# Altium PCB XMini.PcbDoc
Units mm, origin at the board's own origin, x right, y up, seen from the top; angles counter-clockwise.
Board outline 108 x 108 mm, 2 copper layers (Top Layer, Bottom Layer); 86 components, 103 nets, 331 pads, 182 vias.
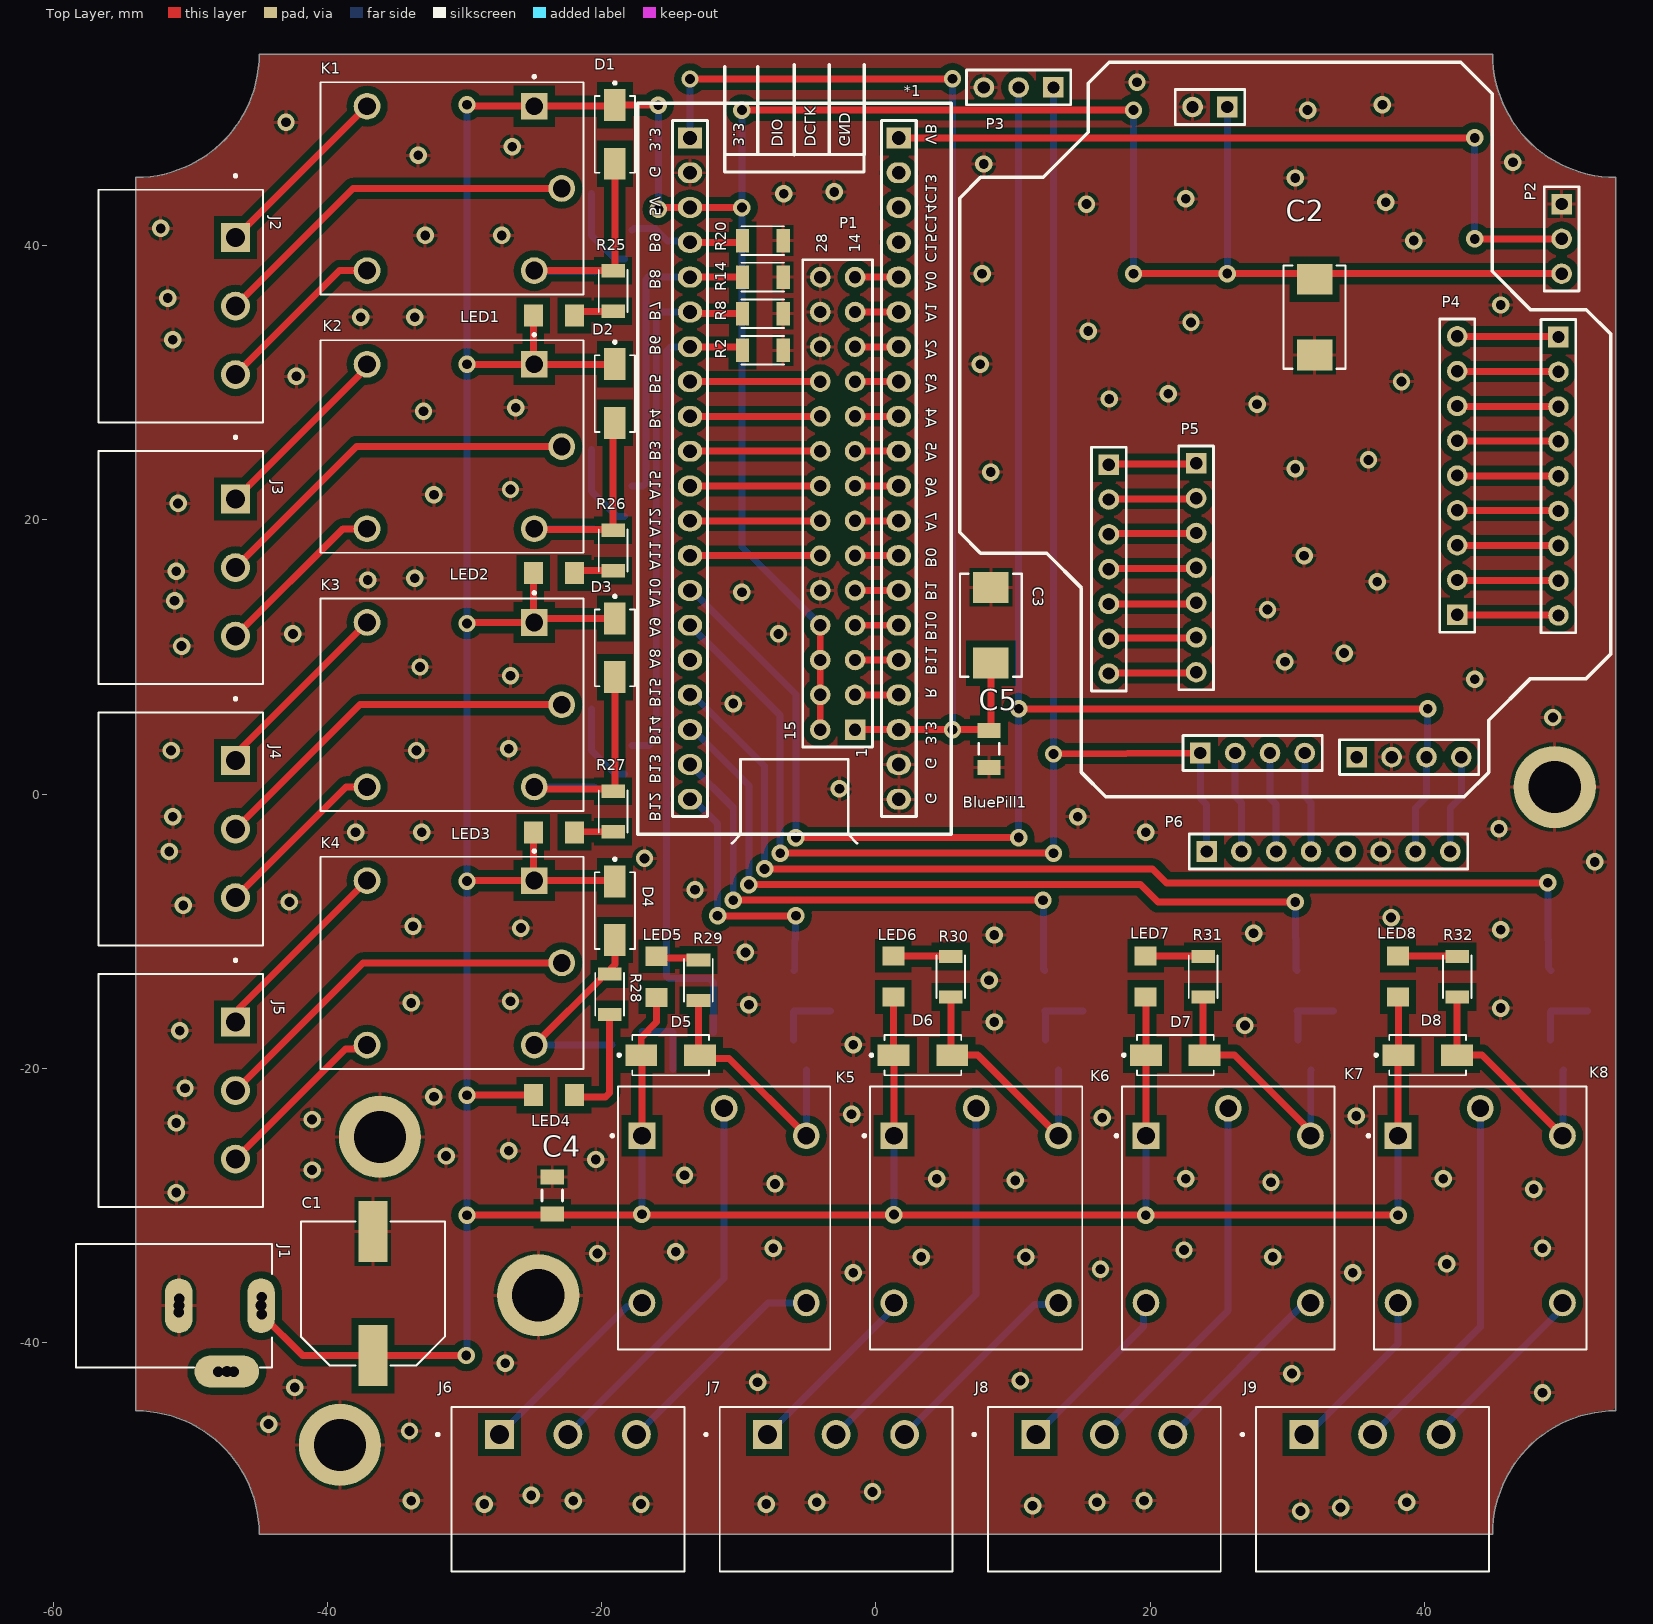
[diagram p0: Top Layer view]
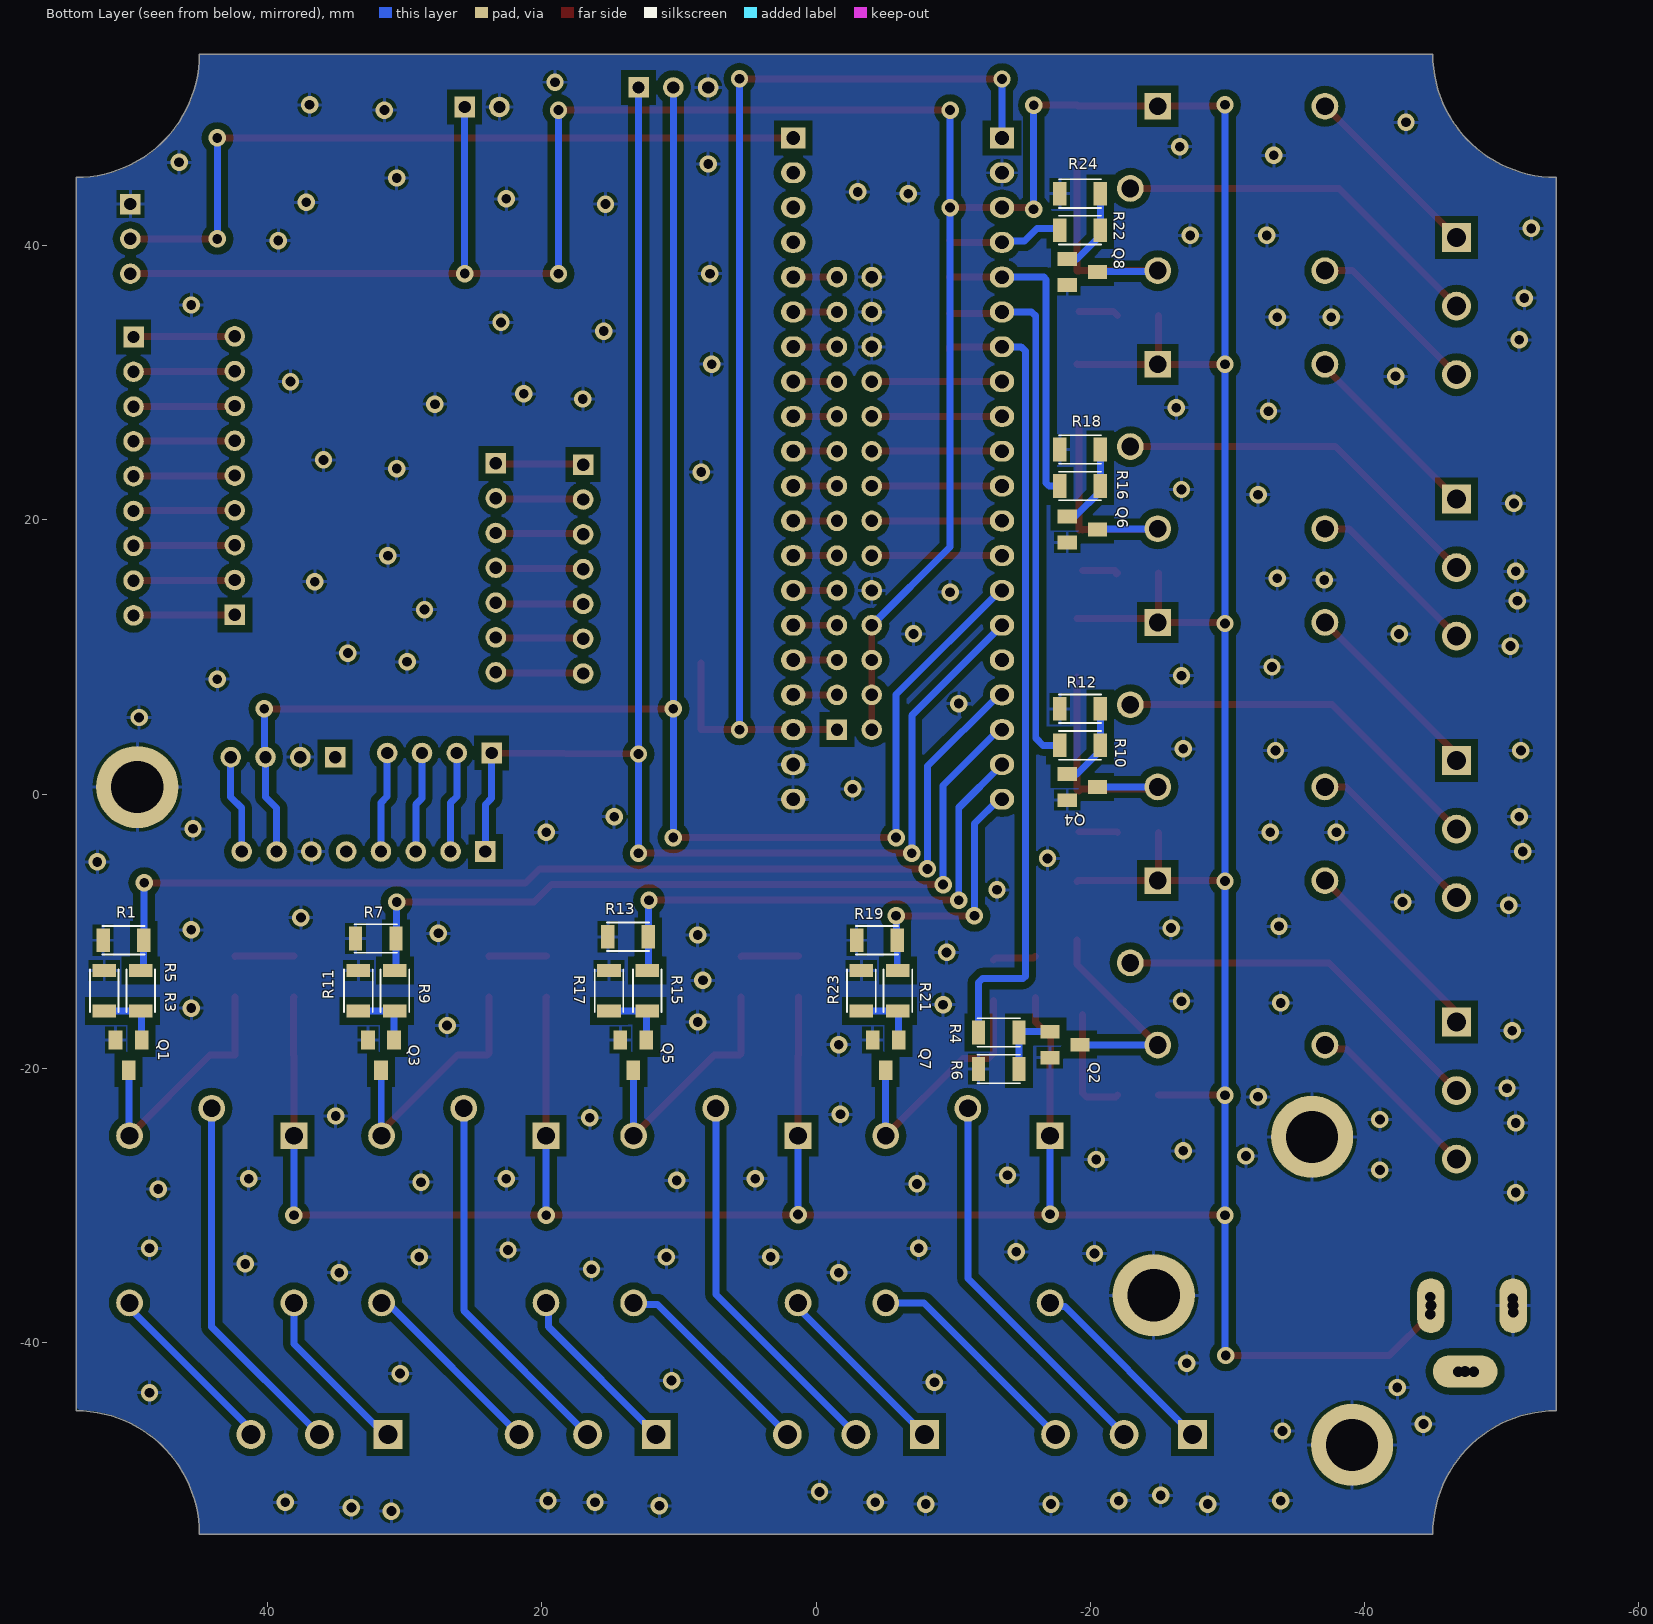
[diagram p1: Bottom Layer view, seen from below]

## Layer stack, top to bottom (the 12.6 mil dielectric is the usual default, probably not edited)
Top Solder: solder mask 0.0102, Solder Resist, Dk 3.5
Top Layer: signal copper 0.0356
Dielectric 1: dielectric 0.32, FR-4, Dk 4.8
Bottom Layer: signal copper 0.0356
Bottom Solder: solder mask 0.0102, Solder Resist, Dk 3.5

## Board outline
-54,-45 -54,45 ccw(c-54,54) -45,54 45,54 ccw(c54,54) 54,45 54,-45 ccw(c54,-54) 45,-54 -45,-54 ccw(c-54,-54)

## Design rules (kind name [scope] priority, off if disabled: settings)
Clearance [All] p1: gap=0.254 ignorepadtopadclearanceinfootprint=FALSE except(0: Arc-Hole Track-Hole SMDPad-Hole THPad-Hole Via-Hole Fill-Hole Poly-Hole Region-Hole Text-Hole; 0.508: Arc-Poly Track-Poly SMDPad-Poly THPad-Poly Via-Poly Fill-Poly Poly-Poly)
PolygonConnect [All] p1: connectstyle=Relief reliefconductorwidth=0.254 reliefentries=4 polygonreliefangle="90 Angle" airgapwidth=0.254
RoutingVias [All] p1: holewidth=0.711 width=1.27 viastyle="Through Hole" minholewidth=0.711 minwidth=1.27 maxholewidth=0.711 maxwidth=1.27
SolderMaskExpansion [All] p1: expansion=0.102
Width [All] p1: maxlimit=0.508 minlimit=0.508 preferedwidth=0.508
30 further rules are at their usual default settings.

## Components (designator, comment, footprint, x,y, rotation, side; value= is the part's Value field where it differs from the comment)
*1 "Component_1" Lora_Board 33.401,26.416 r0 top locked
BluePill1 "BluePill" "stm32 Blue pill" -17.254,-2.794 r0 top locked
C1 "1000uF" *CAPAE1030X1050N -36.703,-36.449 r90 top
C2 "100uF" *CAPCP7343X430N 32.004,34.798 r270 top
C3 "100uF" *CAPCP7343X430N 8.382,12.319 r90 top
C4 "Cap Semi" C1206 -23.622,-29.29 r270 top value=100nF
C5 "Cap Semi" C1206 8.255,3.302 r90 top value=100nF
D1 "S1M" "SMD Diode*DIOM5227X270NSMD DiodeS1MSMD DiodePrimarySMD Diode" -19.05,48.133 r270 top
D2 "S1M" "SMD Diode*DIOM5227X270NSMD DiodeS1MSMD DiodePrimarySMD Diode" -19.05,29.229 r270 top
D3 "S1M" "SMD Diode*DIOM5227X270NSMD DiodeS1MSMD DiodePrimarySMD Diode" -19.05,10.668 r270 top
D4 "S1M" "SMD Diode*DIOM5227X270NSMD DiodeS1MSMD DiodePrimarySMD Diode" -19.05,-8.509 r270 top
D5 "S1M" "SMD Diode*DIOM5227X270NSMD DiodeS1MSMD DiodePrimarySMD Diode" -14.986,-19.05 r0 top
D6 "S1M" "SMD Diode*DIOM5227X270NSMD DiodeS1MSMD DiodePrimarySMD Diode" 3.429,-19.05 r0 top
D7 "S1M" "SMD Diode*DIOM5227X270NSMD DiodeS1MSMD DiodePrimarySMD Diode" 21.844,-19.05 r0 top
D8 "S1M" "SMD Diode*DIOM5227X270NSMD DiodeS1MSMD DiodePrimarySMD Diode" 40.259,-19.05 r0 top
J1 "DC-005" *NINIGI_DC-005 -47.371,-37.338 r0 top locked
J2 "1757488" *PHOENIX_1757488 -46.736,40.687 r270 top locked
J3 "1757488" *PHOENIX_1757488 -46.736,21.606 r270 top locked
J4 "1757488" *PHOENIX_1757488 -46.736,2.524 r270 top locked
J5 "1757488" *PHOENIX_1757488 -46.736,-16.557 r270 top locked
J6 "1757488" *PHOENIX_1757488 -27.559,-46.736 r0 top locked
J7 "1757488" *PHOENIX_1757488 -7.985,-46.736 r0 top locked
J8 "1757488" *PHOENIX_1757488 11.588,-46.736 r0 top locked
J9 "1757488" *PHOENIX_1757488 31.162,-46.736 r0 top locked
K1 "1-1721150-0" *TE_ORWH-SH-105D1F,000 -24.935,50.196 r180 top locked
K2 "1-1721150-0" *TE_ORWH-SH-105D1F,000 -24.935,31.358 r180 top locked
K3 "1-1721150-0" *TE_ORWH-SH-105D1F,000 -24.935,12.519 r180 top locked
K4 "1-1721150-0" *TE_ORWH-SH-105D1F,000 -24.935,-6.319 r180 top locked
K5 "1-1721150-0" *TE_ORWH-SH-105D1F,000 -17.08,-24.935 r270 top locked
K6 "1-1721150-0" *TE_ORWH-SH-105D1F,000 1.313,-24.935 r270 top locked
K7 "1-1721150-0" *TE_ORWH-SH-105D1F,000 19.707,-24.935 r270 top locked
K8 "1-1721150-0" *TE_ORWH-SH-105D1F,000 38.1,-24.935 r270 top locked
LED1 "Red" *LED_597-3111-407F -23.495,34.925 r180 top
LED2 "Red" *LED_597-3111-407F -23.495,16.129 r180 top
LED3 "Red" *LED_597-3111-407F -23.495,-2.794 r180 top
LED4 "Red" *LED_597-3111-407F -23.495,-21.971 r180 top
LED5 "Red" *LED_597-3111-407F -16.002,-13.335 r270 top
LED6 "Red" *LED_597-3111-407F 1.27,-13.31 r270 top
LED7 "Red" *LED_597-3111-407F 19.685,-13.31 r270 top
LED8 "Red" *LED_597-3111-407F 38.1,-13.31 r270 top
P1 "Header 14X2A" HDR2X14_CEN -1.524,4.699 r90 top
P2 "Header 3" HDR1X3 50.038,43.053 r270 top locked
P3 "Header 3" HDR1X3 12.954,51.562 r180 top locked
P4 "Header 9" HDR1X9 42.418,13.081 r90 top locked
P5 "Header 7" HDR1X7 23.368,24.13 r270 top locked
P6 "Header 8" HDR1X8 24.13,-4.191 r0 top locked
Q1 "2N7002" *SOT23 50.165,-19.05 r0 bottom
Q2 "2N7002" *SOT23 -18.161,-18.288 r270 bottom
Q3 "2N7002" *SOT23 31.75,-19.05 r0 bottom
Q4 "2N7002" *SOT23 -19.431,0.508 r270 bottom
Q5 "2N7002" *SOT23 13.335,-19.05 r0 bottom
Q6 "2N7002" *SOT23 -19.431,19.304 r270 bottom
Q7 "2N7002" *SOT23 -5.08,-19.05 r0 bottom
Q8 "2N7002" *SOT23 -19.431,38.1 r270 bottom
R1 "10K" *RESC3116X65N 50.546,-10.668 r0 bottom
R2 "10K" *RESC3116X65N -8.255,32.385 r0 top
R3 "100" *RESC3116X65N 49.276,-14.351 r270 bottom
R4 "100" *RESC3116X65N -13.335,-17.399 r180 bottom
R5 "100K" *RESC3116X65N 51.943,-14.351 r90 bottom
R6 "100K" *RESC3116X65N -13.335,-20.066 r0 bottom
R7 "10K" *RESC3116X65N 32.131,-10.541 r0 bottom
R8 "10K" *RESC3116X65N -8.255,35.052 r0 top
R9 "100" *RESC3116X65N 30.734,-14.351 r270 bottom
R10 "100" *RESC3116X65N -19.266,3.556 r180 bottom
R11 "100K" *RESC3116X65N 33.401,-14.351 r90 bottom
R12 "100K" *RESC3116X65N -19.266,6.223 r0 bottom
R13 "10K" *RESC3116X65N 13.716,-10.414 r0 bottom
R14 "10K" *RESC3116X65N -8.255,37.719 r0 top
R15 "100" *RESC3116X65N 12.319,-14.351 r270 bottom
R16 "100" *RESC3116X65N -19.266,22.479 r180 bottom
R17 "100K" *RESC3116X65N 15.113,-14.351 r90 bottom
R18 "100K" *RESC3116X65N -19.266,25.146 r0 bottom
R19 "10K" *RESC3116X65N -4.445,-10.668 r0 bottom
R20 "10K" *RESC3116X65N -8.255,40.386 r0 top
R21 "100" *RESC3116X65N -5.969,-14.351 r270 bottom
R22 "100" *RESC3116X65N -19.266,41.148 r180 bottom
R23 "100K" *RESC3116X65N -3.302,-14.351 r90 bottom
R24 "100K" *RESC3116X65N -19.266,43.815 r0 bottom
R25 "1K" *RESC3116X65N -19.177,36.703 r90 top
R26 "1K" *RESC3116X65N -19.177,17.78 r90 top
R27 "1K" *RESC3116X65N -19.177,-1.27 r90 top
R28 "1K" *RESC3116X65N -19.431,-14.605 r90 top
R29 "1K" *RESC3116X65N -12.954,-13.589 r270 top
R30 "1K" *RESC3116X65N 5.461,-13.335 r270 top
R31 "1K" *RESC3116X65N 23.876,-13.335 r270 top
R32 "1K" *RESC3116X65N 42.418,-13.335 r270 top

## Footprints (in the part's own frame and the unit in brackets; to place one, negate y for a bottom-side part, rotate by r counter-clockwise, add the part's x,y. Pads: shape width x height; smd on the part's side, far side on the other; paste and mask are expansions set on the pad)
*CAPAE1030X1050N [mm]
  rect 4.46x2.12 smd: 1(-4.525,0) 2(4.525,0)
  silkscreen extent -5.25,-5.25 5.25,5.25
*CAPCP7343X430N [mil]
  rect 89x102 smd: 1(-109,0) 2(109,0)
  silkscreen extent -148,-89 148,89
*LED_597-3111-407F [mil]
  rect 55x63 smd: 1(-59,0) 2(59,0)
*NINIGI_DC-005 [mm]
  oval 4.7x2.35 hole 0.8: 2(0,-4.8)
  oval 2x4 hole 0.8: 3(-3.5,0) 4(2.5,0)
  silkscreen extent -11,-4.5 3.3,4.5
*PHOENIX_1757488 [mm]
  rect 2.1x2.1 hole 1.4: 1(0.08,0)
  round 2.1 hole 1.4: 2(5.08,0) 3(10.08,0)
  silkscreen extent -4.52,-10 13.58,2
*RESC3116X65N [mm]
  rect 0.97x1.73 smd: 1(-1.48,0) 2(1.48,0)
  silkscreen extent -1.55,-1.05 1.55,1.05
*SOT23 [mm]
  rect 1x1.4 smd: 1(-0.95,-1.1) 2(0.95,-1.1) 3(0,1.1)
*TE_ORWH-SH-105D1F,000 [mm]
  rect 1.95x1.95 hole 1.3: 1(0,0)
  round 1.95 hole 1.3: 2(0,12) 3(-2,6) 4(12.2,0) 5(12.2,12)
  silkscreen extent -3.6,-2.26 15.6,13.75
C1206 [mm] "Chip Capacitor, Body 3.2x1.6mm, IPC High Density"
  rect 1.1x1.7 smd: 1(-1.35,0) 2(1.35,0)
  silkscreen extent -0.4,-0.75 0.4,0.75, body extent -1.7,-0.9 1.7,0.9, height 1.3
HDR1X3 [mm] "Connector; Header; 3 Position"
  rect 1.5x1.5 hole 0.9: 1(0,0)
  round 1.5 hole 0.9: 2(2.54,0) 3(5.08,0)
  silkscreen extent -1.27,-1.27 6.35,1.27
HDR1X7 [mm] "Connector; Header; 7 Position"
  rect 1.5x1.5 hole 0.9: 1(0,0)
  round 1.5 hole 0.9: 2(2.54,0) 3(5.08,0) 4(7.62,0) 5(10.16,0) 6(12.7,0) 7(15.24,0)
  silkscreen extent -1.27,-1.27 16.51,1.27
HDR1X8 [mm] "Connector; Header; 8 Position"
  rect 1.5x1.5 hole 0.9: 1(0,0)
  round 1.5 hole 0.9: 2(2.54,0) 3(5.08,0) 4(7.62,0) 5(10.16,0) 6(12.7,0) 7(15.24,0) 8(17.78,0)
  silkscreen extent -1.27,-1.27 19.05,1.27
HDR1X9 [mm] "Connector; Header; 9 Position"
  rect 1.5x1.5 hole 0.9: 1(0,0)
  round 1.5 hole 0.9: 2(2.54,0) 3(5.08,0) 4(7.62,0) 5(10.16,0) 6(12.7,0) 7(15.24,0) 8(17.78,0) 9(20.32,0)
  silkscreen extent -1.27,-1.27 21.59,1.27
HDR2X14_CEN [mm] "Connector; Header; 14x2 Position"
  rect 1.5x1.5 hole 0.9: 1(0,0)
  round 1.5 hole 0.9: 2(2.54,0) 3(5.08,0) 4(7.62,0) 5(10.16,0) 6(12.7,0) 7(15.24,0) 8(17.78,0) 9(20.32,0) 10(22.86,0) 11(25.4,0) 12(27.94,0) 13(30.48,0) 14(33.02,0) 15(0,2.54) 16(2.54,2.54) 17(5.08,2.54) 18(7.62,2.54) 19(10.16,2.54) 20(12.7,2.54) 21(15.24,2.54) 22(17.78,2.54) 23(20.32,2.54) 24(22.86,2.54) 25(25.4,2.54) 26(27.94,2.54) 27(30.48,2.54) 28(33.02,2.54)
  silkscreen extent -1.27,-1.27 34.29,3.81
Lora_Board [mm] "Parvizi Lora Board"
  rect 1.5x1.5 hole 0.9: E1(1.694,-23.722) PA0(-16.404,-2.382) PA3(-9.726,-23.422) PA8(16.404,6.938) VCC(-7.756,23.722)
  round 1.5 hole 0.9: GND(-10.296,23.722) GND(4.234,-23.722) MISO(16.404,-5.762) MOSI(16.404,-8.302) NSS(16.404,-0.682) PA9(16.404,4.398) PA10(16.404,1.858) PA15(-2.106,-23.422) PB3(-4.646,-23.422) PB4(-7.186,-23.422) PB5(-16.404,-17.622) PC13(-16.404,-4.922) SCK(16.404,-3.222) SCL(-16.404,-10.002) SDA(-16.404,-7.462) SWCLK(6.774,-23.722) SWDIO(9.314,-23.722) USART_CTS(16.404,-10.842) USART_RTS(16.404,-13.382) USART_RX(-16.404,-12.542) USART_TX(-16.404,-15.082)
  silkscreen extent -27.29,-26.62 20.2,26.97
"SMD Diode*DIOM5227X270NSMD DiodeS1MSMD DiodePrimarySMD Diode" [mm]
  rect 2.33x1.56 smd: A(2.14,0) C(-2.14,0)
  silkscreen extent -3.85,-1.47 2.8,1.47
"stm32 Blue pill" [mil] "BluePill"
  rect 70x60 hole 39.37: 1(745,1995) 40(145,1995)
  oval 70x60 hole 39.37: 2(745,1895) 3(745,1795) 4(745,1695) 5(745,1595) 6(745,1495) 7(745,1395) 8(745,1295) 9(745,1195) 10(745,1095) 11(745,995) 12(745,895) 13(745,795) 14(745,695) 15(745,595) 16(745,495) 17(745,395) 18(745,295) 19(745,195) 20(745,95) 21(145,95) 22(145,195) 23(145,295) 24(145,395) 25(145,495) 26(145,595) 27(145,695) 28(145,795) 29(145,895) 30(145,995) 31(145,1095) 32(145,1195) 33(145,1295) 34(145,1395) 35(145,1495) 36(145,1595) 37(145,1695) 38(145,1795) 39(145,1895)
  silkscreen extent -5,-32 895,2205

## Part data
BluePill1: library part Stm32BluePill, "Blue Pill Module"
C1: library part HZA107M050G24T-F, "Cap Aluminum Polymer Hybrid 100uF 50VDC 20% _10 X 10.2mm_ SMD 0.028 Ohm 2000mA 10000h 105C Automotive T/R", Package="Radial Cornell Dubilier"
C2 C3: library part TAJE337K006R, "Capacitor tantalum TAJ 2717 330uF 6.3V", Package=None
C4 C5: "Capacitor (Semiconductor SIM Model)"
D1 D2 D3 D4 D5 D6 D7 D8: "S1 Series 1000 V 1 A 1 uA Surface Mount General Purpose Rectifier - DO-214AC", Package="DO-214AC-214 ON Semiconductor"
J1: Package="0603 Ninigi"
J2 J3 J4 J5 J6 J7 J8 J9: "Conn; TermBlk; PCB; Header; SnglLvl; 90DegAngl; Sldr; 3Pole; 5mmPitch; COMBICON", Package=None
K1 K2 K3 K4 K5 K6 K7 K8: library part ORWH-SH-105D1F,000, "General Purpose Relay, ORWH Series, Power, Non Latching, SPDT, 5 VDC, 10 A", Package=None
LED1 LED2 LED3 LED4 LED5 LED6 LED7 LED8: library part 597-3111-407F, "LED RED CLEAR 1206 SMD", Package="1206 Dialight"
P1: "Header, 14-Pin, Dual row"
P2 P3: "Header, 3-Pin"
P4: "Header, 9-Pin"
P5: "Header, 7-Pin"
P6: "Header, 8-Pin"
Q1 Q2 Q3 Q4 Q5 Q6 Q7 Q8: "Transistor NPN Mos 2N7002 SILICONIX miliampere=100 V=60 SOt23", Package="SOT-23-3 Vishay"
R1 R2 R3 R4 R5 R6 R7 R8 R9 R10 R11 R12 R13 R14 R15 R16 R17 R18 R19 R20 R21 R22 R23 R24 R25 R26 R27 R28 R29 R30 R31 R32: library part RT1206DRE07120KL, "Res Smd 120k Ohm 0.5% 1/8w 1206", Package="1206 Yageo"

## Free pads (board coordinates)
  round 1.524 hole 0.762: 2(-44.831,-37.973) 3(-44.831,-36.703) 4(-46.863,-42.164) 5(-48.006,-42.164) 6(-50.876,-37.821) 7(-50.851,-36.83)
  round 6 hole 3.81: 5(-39.116,-47.498) 5(-36.195,-25.019) 5(-24.638,-36.576) 5(49.53,0.508)

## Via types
v1: diameter 1.27, hole 0.711, Top Layer to Bottom Layer, tented both sides, 182 vias

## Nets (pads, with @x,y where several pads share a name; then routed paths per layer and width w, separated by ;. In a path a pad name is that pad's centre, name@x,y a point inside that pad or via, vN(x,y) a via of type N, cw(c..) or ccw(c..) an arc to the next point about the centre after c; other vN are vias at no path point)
3.3V: BluePill1.18 BluePill1.40 C3.1 C5.2 P1.1 | length 85.7
  Top Layer w0.508: v1(-13.571,52.179) 5.57,52.179 v1(5.588,52.197) ; P1.1 BluePill1.18 v1(5.588,4.699) 8.382,4.699 C3.1
  Bottom Layer w0.508: v1@-13.589,52.197 v1(-13.571,52.179) BluePill1.40 ; v1(5.588,4.699) v1(5.588,52.197)
5V: *1.VCC BluePill1.38 C1.1 C2.1 C4.2 D1.C D2.C D3.C D4.C D5.C D6.C D7.C D8.C J1.4 K1.1 K2.1 K3.1 K4.1 K5.1 K6.1 K7.1 K8.1 LED1.2 LED2.2 LED3.2 LED4.2 LED5.2 LED6.2 LED7.2 LED8.2 P1.15 P1.16 P1.17 P1.18 P2.3 pad.2 pad.3 | length 447.2
  Top Layer w0.508: pad.2 -41.83,-40.974 C1.1 v1(-29.892,-40.974) ; v1(-29.845,-30.734) v1(19.685,-30.734) v1@37.973,-30.734 ; v1(-29.845,-21.971) LED4.2 ; v1(-29.845,-6.35) -29.814,-6.319 K4.1 ; v1@-29.845,12.573 -29.791,12.519 K3.1 ; v1(-29.845,31.369) -29.834,31.358 K2.1 ; v1@-29.845,50.165 -29.814,50.196 K1.1 -19.127,50.196 D1.C v1(-15.894,50.273) v1@-15.875,50.292 ; LED3.2 -24.994,-6.26 K4.1 ; LED2.2 -24.994,12.578 K3.1 ; LED1.2 -24.994,31.416 K2.1 ; D4.C -19.1,-6.319 K4.1 ; D3.C -24.646,12.808 K3.1 ; D2.C -19.061,31.358 K2.1 ; K5.1 -17.08,-19.096 D5.C -17.126,-17.761 -16.002,-16.637 LED5.2 ; v1@-16.129,42.799 BluePill1.38 v1(-9.779,42.799) ; v1(-9.779,49.911) v1(18.796,49.911) ; P1.15 P1.16 P1.17 P1.18 ; LED6.2 1.289,-14.827 D6.C 1.313,-19.074 K6.1 ; v1(18.796,37.973) P2.3 ; LED7.2 19.704,-14.827 D7.C 19.707,-19.053 K7.1 ; K8.1 38.1,-19.069 D8.C 38.119,-14.827 LED8.2
  Bottom Layer w0.508: v1@-29.845,-40.974 v1(-29.845,-30.734) v1(-29.845,-21.971) v1(-29.845,-6.35) v1(-29.845,12.446) v1(-29.845,31.369) v1(-29.845,50.292) ; v1@-17.145,-30.734 v1(-17.08,-30.669) K5.1 ; v1(-15.875,42.672) v1@-15.875,50.292 ; v1(-9.779,49.911) v1(-9.779,42.799) -9.779,18.034 P1.18 ; v1@1.27,-30.734 v1(1.313,-30.691) K6.1 ; v1(18.796,37.973) v1(18.796,49.911) ; v1(19.685,-30.734) 19.707,-30.712 K7.1 ; *1.VCC v1(25.645,37.982) v1@25.654,37.973 ; v1(38.1,-30.734) K8.1
GND: *1.GND BluePill1.19 BluePill1.20 BluePill1.39 C1.2 C2.2 C3.2 C4.1 C5.1 J1.3 P1.19 P1.26 P1.27 P1.28 P2.1 P3.3 P6.6 pad.5@49.53,0.508 pad.5@-24.638,-36.576 pad.5@-36.195,-25.019 pad.5@-39.116,-47.498 pad.6 pad.7 Q1.2 Q2.2 Q3.2 Q4.2 Q5.2 Q6.2 Q7.2 Q8.2 R1.2 R2.2 R5.2 R6.2 R7.2 R8.2 R11.2 R12.2 R13.2 R14.2 R17.2 R18.2 R19.2 R20.2 R23.2 R24.2
  other v1: 30.988,-52.324 33.909,-52.07 11.43,-51.943 -28.575,-51.816 -17.145,-51.816 -8.001,-51.816 -4.318,-51.689 16.129,-51.689 38.735,-51.689 -33.909,-51.562 -22.098,-51.562 19.558,-51.562 -25.146,-51.181 -0.254,-50.927 -34.036,-46.482 -44.323,-45.974 48.641,-43.688 -42.418,-43.307 -8.636,-42.926 10.541,-42.799 30.353,-42.291 -27.051,-41.529 -1.651,-34.925 34.798,-34.925 16.383,-34.671 41.656,-34.29 3.302,-33.782 10.922,-33.782 28.956,-33.782 -20.32,-33.528 -14.605,-33.401 22.479,-33.274 -7.493,-33.147 48.641,-33.147 -51.054,-29.083 48.006,-28.829 -7.366,-28.448 28.829,-28.321 10.16,-28.194 4.445,-28.067 22.606,-28.067 41.402,-28.067 -13.97,-27.813 -41.148,-27.432 -20.447,-26.67 -31.369,-26.416 -26.797,-26.035 -51.054,-24.003 -41.148,-23.749 16.51,-23.622 35.052,-23.495 -1.778,-23.368 -32.258,-22.098 -50.419,-21.463 -1.651,-18.288 -50.8,-17.272 26.924,-16.891 8.636,-16.637 45.593,-15.621 -9.271,-15.367 -33.909,-15.24 -26.67,-15.113 8.255,-13.589 -9.525,-11.557 8.636,-10.287 27.559,-10.16 45.593,-9.906 -25.908,-9.779 -33.782,-9.652 37.592,-9.017 -50.546,-8.128 -42.799,-7.874 -13.208,-6.985 52.451,-4.953 -16.891,-4.699 -51.562,-4.191 -37.973,-2.794 -33.147,-2.794 19.685,-2.794 45.466,-2.54 -51.308,-1.651 14.732,-1.651 -2.667,0.381 -51.435,3.175 -33.528,3.175 -26.797,3.302 49.403,5.588 -10.414,6.604 43.688,8.382 -26.67,8.636 -33.274,9.271 29.845,9.652 34.163,10.287 -50.673,10.795 -42.545,11.684 -7.112,11.684 28.575,13.462 -51.181,14.097 -9.779,14.732 36.576,15.494 -37.084,15.621 -33.655,15.748 -51.054,16.256 31.242,17.399 -50.927,21.209 -32.258,21.844 -26.67,22.225 8.382,23.495 30.607,23.749 35.941,24.384 -33.02,27.94 -26.289,28.194 27.813,28.448 17.018,28.829 21.336,29.21 38.354,30.099 -42.291,30.48 7.62,31.369 -51.308,33.147 15.494,33.782 22.987,34.417 -37.592,34.798 -33.655,34.798 45.593,35.687 -51.689,36.195 7.747,37.973 39.243,40.386 -32.893,40.767 -27.305,40.767 -52.197,41.275 15.367,43.053 37.211,43.18 22.606,43.434 -6.731,43.815 -3.048,43.942 30.607,44.958 7.874,45.974 46.482,46.101 -33.401,46.609 -26.543,47.244 -43.053,49.022 31.496,49.911 36.957,50.292 19.05,51.943
LPA0: *1.PA0 P5.1 | length 6.4
  Top Layer w0.508: *1.PA0 17.045,24.082 23.32,24.082 P5.1
LPA3: *1.PA3 BluePill1.26 P3.1 P6.1 | length 113.3
  Top Layer w0.508: v1(-6.985,-4.318) v1(12.954,-4.318) ; v1(12.954,2.921) *1.PA3
  Bottom Layer w0.508: BluePill1.26 -6.985,5.733 v1(-6.985,-4.318) ; v1(12.954,-4.318) v1(12.954,2.921) P3.1 ; *1.PA3 23.675,-0.307 24.13,-0.762 P6.1
LPA8: *1.PA8 P4.9 | length 7.4
  Top Layer w0.508: P4.9 42.441,33.378 49.781,33.378 *1.PA8
LPA9: *1.PA9 P4.8 | length 7.4
  Top Layer w0.508: P4.8 42.441,30.838 49.781,30.838 *1.PA9
LPA10: *1.PA10 P4.7 | length 7.4
  Top Layer w0.508: P4.7 42.441,28.298 49.781,28.298 *1.PA10
LPA15: *1.PA15 P6.4 | length 7.4
  Bottom Layer w0.508: *1.PA15 31.295,-0.18 31.75,-0.635 P6.4
LPB3: *1.PB3 P6.3 | length 7.4
  Bottom Layer w0.508: *1.PB3 28.755,-0.307 29.21,-0.762 P6.3
LPB4: *1.PB4 P6.2 | length 7.4
  Bottom Layer w0.508: *1.PB4 26.215,-0.18 26.67,-0.635 P6.2
LPB5: *1.PB5 P5.7 | length 6.4
  Top Layer w0.508: *1.PB5 17.045,8.842 23.32,8.842 P5.7
LPC13: *1.PC13 P5.2 | length 6.4
  Top Layer w0.508: *1.PC13 17.045,21.542 23.32,21.542 P5.2
MISO: *1.MISO P4.4 | length 7.4
  Top Layer w0.508: P4.4 42.441,20.678 49.781,20.678 *1.MISO
MOSI: *1.MOSI P4.3 | length 7.4
  Top Layer w0.508: P4.3 42.441,18.138 49.781,18.138 *1.MOSI
NC: P6.5
NetJ2_1: J2.1 K1.4 | length 13.6
  Top Layer w0.508: J2.1 -37.147,50.196 K1.4
NetJ2_2: J2.2 K1.3 | length 27.4
  Top Layer w0.508: J2.2 -38.147,44.196 K1.3
NetJ2_3: J2.3 K1.5 | length 12.7
  Top Layer w0.508: J2.3 -39.147,38.196 K1.5
NetJ3_1: J3.1 K2.4 | length 13.8
  Top Layer w0.508: J3.1 -37.135,31.127 K2.4
NetJ3_2: J3.2 K2.3 | length 27.5
  Top Layer w0.508: J3.2 -37.904,25.358 K2.3
NetJ3_3: J3.3 K2.5 | length 12.8
  Top Layer w0.508: J3.3 -38.904,19.358 K2.5
NetJ4_1: J4.1 K3.4 | length 14.1
  Top Layer w0.508: J4.1 -46.736,2.918 K3.4
NetJ4_2: J4.2 K3.3 | length 27.6
  Top Layer w0.508: J4.2 -37.661,6.519 K3.3
NetJ4_3: J4.3 K3.5 | length 12.9
  Top Layer w0.508: J4.3 -38.661,0.519 K3.5
NetJ5_1: J5.1 K4.4 | length 14.3
  Top Layer w0.508: J5.1 -46.736,-15.92 K4.4
NetJ5_2: J5.2 K4.3 | length 27.7
  Top Layer w0.508: J5.2 -37.418,-12.319 K4.3
NetJ5_3: J5.3 K4.5 | length 13
  Top Layer w0.508: J5.3 -38.694,-18.595 -37.411,-18.595 K4.5
NetJ6_1: J6.1 K5.4 | length 14.4
  Bottom Layer w0.508: J6.1 -18.154,-37.411 -17.356,-37.411 K5.4
NetJ6_2: J6.2 K5.3 | length 28.5
  Bottom Layer w0.508: J6.2 -11.08,-35.337 K5.3
NetJ6_3: J6.3 K5.5 | length 16.4
  Bottom Layer w0.508: J6.3 -7.878,-37.135 K5.5
NetJ7_1: J7.1 K6.4 | length 13.4
  Bottom Layer w0.508: J7.1 1.313,-37.517 K6.4
NetJ7_2: J7.2 K6.3 | length 28
  Bottom Layer w0.508: J7.2 7.313,-36.517 K6.3
NetJ7_3: J7.3 K6.5 | length 15.2
  Bottom Layer w0.508: J7.3 11.576,-37.254 13.194,-37.254 K6.5
NetJ8_1: J8.1 K7.4 | length 12.9
  Bottom Layer w0.508: J8.1 19.533,-38.872 19.533,-37.309 K7.4
NetJ8_2: J8.2 K7.3 | length 27.5
  Bottom Layer w0.508: J8.2 25.707,-37.698 K7.3
NetJ8_3: J8.3 K7.5 | length 14.1
  Bottom Layer w0.508: J8.3 31.32,-37.084 31.656,-37.084 K7.5
NetJ9_1: J9.1 K8.4 | length 12.6
  Bottom Layer w0.508: J9.1 31.496,-46.736 38.1,-40.132 K8.4
NetJ9_2: J9.2 K8.3 | length 27.1
  Bottom Layer w0.508: J9.2 44.1,-38.878 K8.3
NetJ9_3: J9.3 K8.5 | length 13.3
  Bottom Layer w0.508: J9.3 41.242,-46.364 50.1,-37.506 K8.5
NetLED1_1: LED1.1 R25.1 | length 2.9
  Top Layer w0.508: LED1.1 -21.698,35.223 R25.1
NetLED2_1: LED2.1 R26.1 | length 2.8
  Top Layer w0.508: LED2.1@-21.913,16.046 LED2.1 -21.825,16.3 R26.1@-19.431,16.3
NetLED3_1: LED3.1 R27.1 | length 2.8
  Top Layer w0.508: LED3.1 -21.952,-2.75 R27.1
NetLED4_1: LED4.1 R28.1 | length 8.5
  Top Layer w0.508: LED4.1 -21.869,-22.098 -19.729,-22.098 -19.431,-21.8 R28.1
NetLED5_1: LED5.1 R29.1 | length 3.2
  Top Layer w0.508: LED5.1 -15.866,-11.973 -13.09,-11.973 R29.1
NetLED6_1: LED6.1 R30.1 | length 4.2
  Top Layer w0.508: LED6.1 1.292,-11.833 5.439,-11.833 R30.1
NetLED7_1: LED7.1 R31.1 | length 4.2
  Top Layer w0.508: LED7.1 19.707,-11.833 23.854,-11.833 R31.1
NetLED8_1: LED8.1 R32.1 | length 4.3
  Top Layer w0.508: LED8.1 38.122,-11.833 42.396,-11.833 R32.1
NetQ1_1: Q1.1 R3.2 R5.1 | length 4.8
  Bottom Layer w0.508: Q1.1 49.215,-15.892 R3.2 R5.1
NetQ2_1: Q2.1 R4.2 R6.1 | length 4.9
  Bottom Layer w0.508: Q2.1 -14.876,-17.338 R4.2 R6.1
NetQ3_1: Q3.1 R9.2 R11.1 | length 4.8
  Bottom Layer w0.508: Q3.1 30.8,-15.897 R9.2 R11.1
NetQ4_1: Q4.1 R10.2 R12.1 | length 6.2
  Bottom Layer w0.508: R12.1 R10.2 -20.746,3.176 -19.028,1.458 Q4.1
NetQ5_1: Q5.1 R15.2 R17.1 | length 4.9
  Bottom Layer w0.508: Q5.1 12.385,-15.897 R15.2 R17.1
NetQ6_1: Q6.1 R16.2 R18.1 | length 6.2
  Bottom Layer w0.508: R18.1 R16.2 -20.746,22.099 -18.901,20.254 Q6.1
NetQ7_1: Q7.1 R21.2 R23.1 | length 4.8
  Bottom Layer w0.508: Q7.1 -6.03,-15.892 R21.2 R23.1
NetQ8_1: Q8.1 R22.2 R24.1 | length 6.2
  Bottom Layer w0.508: R24.1 R22.2 -20.746,40.768 -19.028,39.05 Q8.1
NSS: *1.NSS P4.6 | length 7.4
  Top Layer w0.508: P4.6 42.441,25.758 49.781,25.758 *1.NSS
PA0: BluePill1.5 P1.14 | length 3.2
  Top Layer w0.508: P1.14 BluePill1.5
PA1: BluePill1.6 P1.13 | length 3.2
  Top Layer w0.508: P1.13 BluePill1.6
PA2: BluePill1.7 P1.12 | length 3.2
  Top Layer w0.508: P1.12 BluePill1.7
PA3: BluePill1.8 P1.11 | length 3.2
  Top Layer w0.508: P1.11 BluePill1.8
PA4: BluePill1.9 P1.10 | length 3.2
  Top Layer w0.508: P1.10 BluePill1.9
PA5: BluePill1.10 P1.9 | length 3.2
  Top Layer w0.508: P1.9 BluePill1.10
PA6: BluePill1.11 P1.8 | length 3.2
  Top Layer w0.508: P1.8 BluePill1.11
PA7: BluePill1.12 P1.7 | length 3.2
  Top Layer w0.508: P1.7 BluePill1.12
PA8: BluePill1.25
PA11: BluePill1.28 P1.20 | length 9.5
  Top Layer w0.508: BluePill1.28 P1.20
PA12: BluePill1.29 P1.21 | length 9.5
  Top Layer w0.508: BluePill1.29 P1.21
PA15: BluePill1.30 P1.22 | length 9.5
  Top Layer w0.508: BluePill1.30 P1.22
PB0: BluePill1.13 P1.6 | length 3.2
  Top Layer w0.508: P1.6 BluePill1.13
PB1: BluePill1.14 P1.5 | length 3.2
  Top Layer w0.508: P1.5 BluePill1.14
PB3: BluePill1.31 P1.23 | length 9.5
  Top Layer w0.508: BluePill1.31 P1.23
PB4: BluePill1.32 P1.24 | length 9.5
  Top Layer w0.508: BluePill1.32 P1.24
PB5: BluePill1.33 P1.25 | length 9.5
  Top Layer w0.508: BluePill1.33 P1.25
PB6: BluePill1.34 R2.1 R4.1 | length 58.8
  Top Layer w0.508: BluePill1.34 -9.735,32.639 R2.1
  Bottom Layer w0.508: BluePill1.34 -14.971,32.639 -15.269,32.341 -15.269,-13.306 -15.113,-13.462 -12.153,-13.462 -11.855,-13.76 R4.1
PB7: BluePill1.35 R8.1 R10.1 | length 39.2
  Top Layer w0.508: BluePill1.35 -13.444,35.052 R8.1
  Bottom Layer w0.508: R10.1 -16.554,3.556 -16.031,4.079 -16.031,34.881 -15.733,35.179 BluePill1.35
PB8: BluePill1.36 R14.1 R16.1 | length 23.1
  Top Layer w0.508: BluePill1.36 R14.1
  Bottom Layer w0.508: R16.1 -17.018,22.479 -16.793,22.704 -16.793,37.563 -16.637,37.719 BluePill1.36
PB9: BluePill1.37 R20.1 R22.1 | length 8.6
  Top Layer w0.508: BluePill1.37 -9.862,40.259 R20.1
  Bottom Layer w0.508: R22.1 -17.659,41.275 -16.129,41.275 -15.222,40.368 -13.68,40.368 BluePill1.37
PB10: BluePill1.15 P1.4 | length 3.2
  Top Layer w0.508: P1.4 BluePill1.15
PB11: BluePill1.16 P1.3 | length 3.2
  Top Layer w0.508: P1.3 BluePill1.16
PB12: BluePill1.21 R19.1 R21.1 | length 19.2
  Top Layer w0.508: v1(-11.557,-8.89) v1(-5.842,-8.89)
  Bottom Layer w0.508: BluePill1.21 -13.335,-0.381 -11.557,-2.159 v1(-11.557,-8.89) ; R21.1 -5.925,-12.827 R19.1 -5.884,-10.626 -5.884,-8.932 v1(-5.842,-8.89)
PB13: BluePill1.22 R13.1 R15.1 | length 39.5
  Top Layer w0.508: v1(-10.414,-7.747) v1(12.192,-7.747)
  Bottom Layer w0.508: BluePill1.22 -10.414,-0.998 v1(-10.414,-7.747) ; v1(12.192,-7.747) 12.214,-7.515 12.214,-10.392 R13.1 12.236,-12.788 R15.1
PB14: BluePill1.23 R7.1 R9.1 | length 58.7
  Top Layer w0.508: v1(-9.271,-6.604) 12.665,-6.604 19.304,-6.604 20.574,-7.874 v1(30.607,-7.874)
  Bottom Layer w0.508: BluePill1.23 -13.335,4.699 -9.271,0.635 v1(-9.271,-6.604) ; v1(30.607,-7.874) 30.629,-7.896 30.629,-10.519 R7.1 30.651,-12.788 R9.1
PB15: BluePill1.24 R1.1 R3.1 | length 79.2
  Top Layer w0.508: v1(-8.128,-5.461) 20.193,-5.461 21.209,-6.477 v1(49.022,-6.477)
  Bottom Layer w0.508: BluePill1.24 -13.335,7.239 -8.128,2.032 v1(-8.128,-5.461) ; v1(49.022,-6.477) 49.044,-6.499 49.044,-10.646 R1.1 49.066,-12.661 R3.1
"Relay 1": D1.A K1.2 Q8.3 R25.2 | length 18
  Top Layer w0.508: K1.2 -24.928,38.19 -19.184,38.19 R25.2 ; R25.2@-19.05,38.183 D1.A
  Bottom Layer w0.508: K1.2 -24.887,38.148 -20.579,38.148 Q8.3
"Relay 2": D2.A K2.2 Q6.3 R26.2 | length 17.8
  Top Layer w0.508: K2.2 -24.886,19.309 -19.48,19.309 R26.2@-19.431,19.26 ; R26.2 -19.177,26.962 D2.A
  Bottom Layer w0.508: K2.2@-24.908,19.331 -20.558,19.331 Q6.3
"Relay 3": D3.A K3.2 Q4.3 R27.2 | length 18.5
  Top Layer w0.508: K3.2 -24.78,0.365 -19.332,0.365 R27.2 ; R27.2@-19.05,0.287 D3.A
  Bottom Layer w0.508: K3.2 -24.929,0.514 -20.537,0.514 Q4.3
"Relay 4": D4.A K4.2 Q2.3 R28.2 | length 15.8
  Top Layer w0.508: K4.2 -19.741,-13.125 -19.05,-12.434 D4.A
  Bottom Layer w0.508: K4.2 -24.919,-18.303 -19.277,-18.303 Q2.3
"Relay 5": D5.A K5.2 Q7.3 R29.2 | length 19
  Top Layer w0.508: R29.2 -12.954,-18.942 D5.A -12.592,-19.304 -10.711,-19.304 K5.2
  Bottom Layer w0.508: K5.2 Q7.3
"Relay 6": D6.A K6.2 Q5.3 R30.2 | length 19.3
  Top Layer w0.508: R30.2 5.461,-18.942 D6.A 7.429,-19.05 K6.2
  Bottom Layer w0.508: K6.2 13.324,-24.924 13.324,-20.161 Q5.3
"Relay 7": D7.A K7.2 Q3.3 R31.2 | length 19.4
  Top Layer w0.508: R31.2 23.876,-18.942 D7.A 26.162,-19.05 31.707,-24.595 K7.2
  Bottom Layer w0.508: K7.2 31.728,-24.913 31.728,-20.172 Q3.3
"Relay 8": D8.A K8.2 Q1.3 R32.2 | length 19.2
  Top Layer w0.508: R32.2 42.399,-14.834 D8.A 44.215,-19.05 K8.2
  Bottom Layer w0.508: K8.2 50.132,-24.902 50.132,-20.183 Q1.3
Reset: BluePill1.17 P1.2 | length 3.2
  Top Layer w0.508: P1.2 BluePill1.17
RX1: *1.SWCLK BluePill1.27 P3.2 P6.7 | length 132.9
  Top Layer w0.508: v1(-5.842,-3.175) v1(10.414,-3.175) ; v1(10.414,6.223) v1(40.259,6.223)
  Bottom Layer w0.508: BluePill1.27 -13.444,14.859 -5.842,7.257 v1(-5.842,-3.175) ; v1(10.414,-3.175) v1(10.414,6.223) P3.2 ; P6.7 39.37,-1.016 40.175,-0.211 *1.SWCLK 40.259,2.778 v1(40.259,6.223)
SCK: *1.SCK P4.5 | length 7.4
  Top Layer w0.508: P4.5 42.441,23.218 49.781,23.218 *1.SCK
SCL: *1.SCL P5.4 | length 6.4
  Top Layer w0.508: *1.SCL 17.045,16.462 23.32,16.462 P5.4
SDA: *1.SDA P5.3 | length 6.4
  Top Layer w0.508: *1.SDA 17.045,19.002 23.32,19.002 P5.3
SWDIO: *1.SWDIO P6.8 | length 7.2
  Bottom Layer w0.508: P6.8 41.91,-1.016 42.715,-0.211 *1.SWDIO
USART_CTS: *1.USART_CTS P4.2 | length 7.4
  Top Layer w0.508: P4.2 42.441,15.598 49.781,15.598 *1.USART_CTS
USART_RTS: *1.USART_RTS P4.1 | length 7.4
  Top Layer w0.508: P4.1 42.441,13.058 49.781,13.058 *1.USART_RTS
USART_RX: *1.USART_RX P5.5 | length 6.5
  Top Layer w0.508: *1.USART_RX@17.045,13.922 *1.USART_RX 23.272,13.874 P5.5
USART_TX: *1.USART_TX P5.6 | length 6.4
  Top Layer w0.508: *1.USART_TX 17.045,11.382 23.32,11.382 P5.6
VB: BluePill1.1 P2.2 | length 55.7
  Top Layer w0.508: BluePill1.1 v1(43.688,47.879) ; v1(43.688,40.513) P2.2
  Bottom Layer w0.508: v1(43.688,40.513) v1(43.688,47.879)
pads on no net: *1.E1 BluePill1.2 BluePill1.3 BluePill1.4 J1.2

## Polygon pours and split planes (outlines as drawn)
GND on Bottom Layer "GND_L02_P004" (solid, pour order 4): -44.958,53.975 44.958,53.975 ccw(c53.975,53.975) 53.975,44.958 53.975,-44.958 cw(c53.975,-44.831) 53.975,-44.958 ccw(c53.975,-53.975) 44.958,-53.975 -44.958,-53.975 ccw(c-53.975,-53.975) -53.975,-44.958 -53.975,44.958 ccw(c-53.975,53.975)
GND on Bottom Layer "GND_L02_P000" (solid, pour order 0): -44.958,53.975
GND on Top Layer "GND_L01_P002" (solid, pour order 2): -44.958,53.975 44.958,53.975 ccw(c53.975,53.975) 53.975,44.958 53.975,-44.958 cw(c53.975,-44.831) 53.975,-44.958 ccw(c53.975,-53.975) 44.958,-53.975 -44.958,-53.975 ccw(c-53.975,-53.975) -53.975,-44.958 -53.975,44.958 ccw(c-53.975,53.975)

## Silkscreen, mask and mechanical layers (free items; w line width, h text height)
Mechanical 1:
  region: 2.286,9.017
  region: -45,54
  region: -54.356,53.594
  region: -51.816,53.721
  lines w0.254: -54,-45 cw(c-54,-54) -45,-54 45,-54 cw(c54,-54) 54,-45 54,45 cw(c54,54) 45,54 -45,54 cw(c-54,54) -54,45 -54,-45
